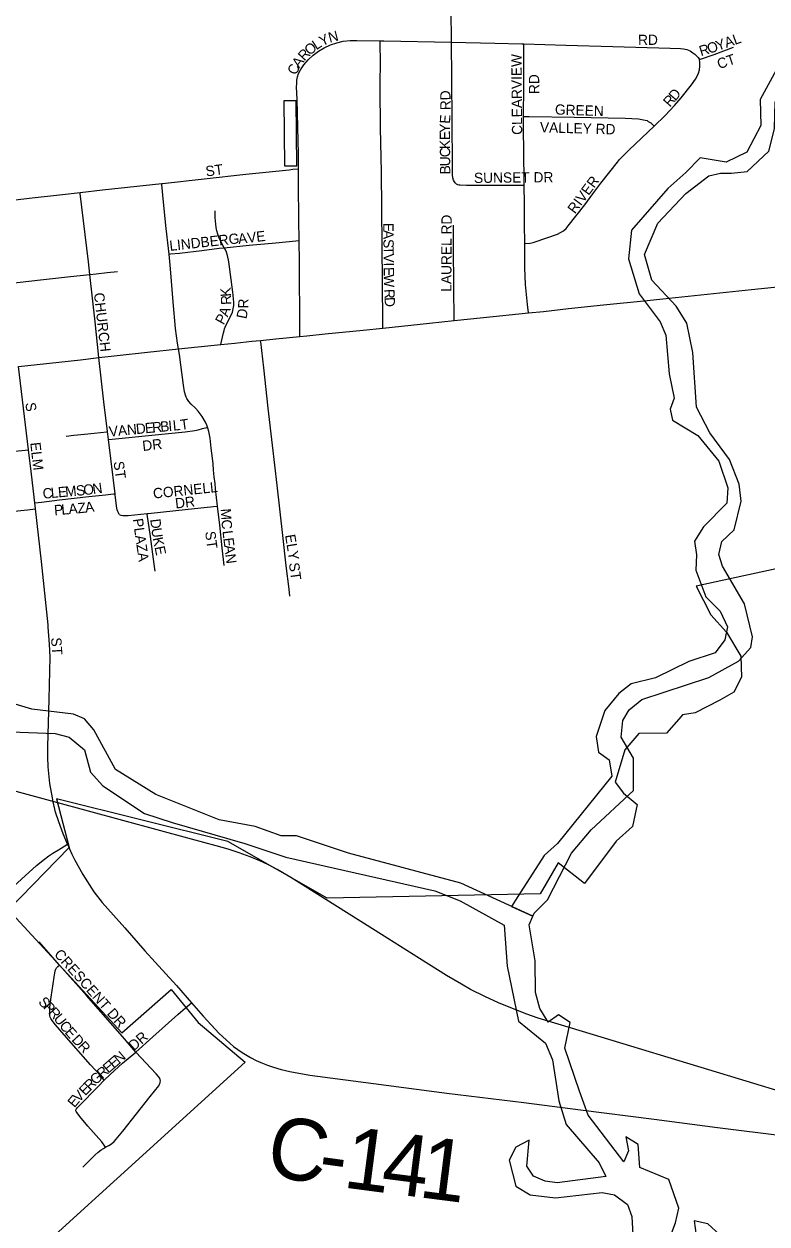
# Model space of a CAD drawing. Extents: x -51392 to 1635000, y 156707 to 696232.
# Drawn here: x 142661 to 146279, y 483748 to 489592 of the extents above; entities that cross this region are included whole.
import ezdxf

# ---------------------------------------------------------------- set-up
doc = ezdxf.new("R2010")
doc.units = 0
for name, color, linetype in [('GM_X_City_Street', 7, 'Continuous'), ('GM_X_City_Street_Text', 7, 'Continuous'), ('GM_X_Corporation', 7, 'Continuous'), ('GM_X_County_Road', 7, 'Continuous'), ('GM_X_County_Road_Text', 7, 'Continuous'), ('GM_X_Major_River', 7, 'Continuous'), ('GM_X_Minor_River', 7, 'Continuous'), ('GM_X_Rail_Line', 7, 'Continuous'), ('GM_X_US_Route', 7, 'Continuous')]:
    doc.layers.add(name, color=color, linetype=linetype)

msp = doc.modelspace()

# ---------------------------------------------------------------- linework, layer by layer
at = {"layer": 'GM_X_City_Street'}
for points in [[(144742.3, 489503.6), (144741.9, 489542.5), (144741.1, 489624.4), (144743.1, 489656.8), (144747.2, 489689.2), (144761.5, 489769.8), (144775.9, 489850.9), (144782.2, 489900), (144786.9, 489965.7), (144792.6, 490146.4), (144800.6, 490392.7), (144803.7, 490507.8), (144806.4, 490539.9), (144809.5, 490555.5), (144813.9, 490570.4), (144820.4, 490584.9), (144828.3, 490598.6), (144837.5, 490611.8), (144921.9, 490712.3), (144964.1, 490763), (144988.3, 490791.5)], [(143990.3, 489224.6), (143988.3, 489286), (143988.5, 489302.4), (143989.7, 489318.8), (143992.6, 489334.9), (143997.6, 489350.5), (144004.6, 489365.4), (144013.1, 489379.4), (144022.8, 489392.7), (144044.4, 489417.4), (144068.3, 489439.9), (144094.4, 489459.8), (144122.4, 489476.8), (144152.3, 489490.3), (144183.4, 489500.9), (144215.4, 489507.9), (144248.1, 489511.7), (144280.9, 489512.4), (144394.7, 489510.4)], [(144407.9, 488111.3), (144407.6, 488136.7), (144405.5, 488332.8), (144401, 488872.1), (144397.1, 489084.5), (144395.5, 489280.6), (144396.5, 489427.7), (144395.7, 489476.7), (144394.7, 489510.4)], [(144394.7, 489510.4), (144412.2, 489510), (144742.3, 489503.6)], [(144760.2, 488818.6), (144756.5, 488823.7), (144752.4, 488831.3), (144749.1, 488842.2), (144747.5, 488857.5), (144747.5, 488906), (144745.2, 489117), (144744, 489327.9), (144742.3, 489503.6)], [(144742.3, 489503.6), (144953.7, 489499.4), (145085.1, 489496.3), (145094, 489496.3)], [(145093.1, 489142.1), (145094, 489287.2), (145094, 489496.3)], [(145094, 489496.3), (145298.3, 489489.3), (145528.1, 489482), (145807.3, 489474.1), (145856.6, 489472.6), (145872.8, 489470.9), (145888.7, 489467.4), (145903.8, 489461.2), (145917.3, 489452), (145927.4, 489444.4), (145935, 489437.7), (145943.5, 489428.9), (145950.4, 489419.5)], [(145950.4, 489419.5), (146021, 489442.8), (146116, 489479.3)], [(145728.7, 489094.6), (145783.1, 489147.1), (145828.3, 489194.5), (145860.3, 489231.8), (145911.3, 489296), (145930.4, 489322.9), (145938.8, 489337.4), (145945.4, 489353.1), (145949.3, 489369.7), (145950.9, 489386.5), (145951.6, 489405.5), (145950.4, 489419.5)], [(143997.5, 488887.2), (143997.5, 488957.9), (143994.8, 489089.1), (143990.3, 489224.6)], [(145096, 488806.7), (145095.7, 488829.5), (145092.8, 489091.1), (145093.1, 489142.1)], [(145093.1, 489142.1), (145120.2, 489142.1), (145340.4, 489138), (145587.3, 489132.7), (145653, 489129.5), (145669.2, 489127.4), (145685.3, 489124.2), (145694.3, 489121.4), (145700.6, 489118), (145712.3, 489110.4), (145719.2, 489104.3), (145728.7, 489094.6)], [(145098.6, 488522.4), (145125.4, 488524.8), (145139.2, 488527.7), (145150, 488530.5), (145257.9, 488569), (145273.2, 488576), (145287.8, 488584.9), (145300.4, 488596.4), (145311.1, 488609.4), (145391.7, 488711.7), (145430.9, 488764.2), (145469.8, 488816.8), (145549.9, 488919.6), (145560.5, 488932), (145571.5, 488943.7), (145605.8, 488978.2), (145700.7, 489067.6), (145728.7, 489094.6)], [(143331, 488815.1), (143335.5, 488815.6), (143741.4, 488861.2), (143951.5, 488882.6), (143969.1, 488884.3), (143997.5, 488887.2)], [(143999.3, 488637.8), (143997.5, 488810.2), (143997.5, 488887.2)], [(142539.4, 488726.3), (142566.4, 488729.3), (142686, 488743.1), (142848.4, 488761.7), (142933.6, 488771.4)], [(142933.6, 488771.4), (143043.1, 488783.8), (143331, 488815.1)], [(142980.8, 488372.3), (142973.9, 488434), (142934.2, 488766.8), (142933.6, 488771.4)], [(143367.9, 488471.6), (143365, 488498.9), (143353.3, 488596.4), (143340.1, 488724.6), (143331.4, 488810.9), (143331, 488815.1)], [(144760.2, 488818.6), (144765.8, 488814), (144770.7, 488811.2), (144777.2, 488809.2), (144784, 488808), (144815.9, 488806.5), (145096, 488806.7)], [(145098.6, 488522.4), (145097, 488617.1), (145097.3, 488715.1), (145096, 488806.7)], [(143636, 488502.4), (143616.3, 488538.5), (143609.6, 488553.7), (143604.5, 488569.1), (143600.3, 488584), (143596.8, 488600.8), (143594.4, 488616.9), (143593.1, 488633.7), (143592.2, 488649.8), (143592, 488682.6)], [(144000.4, 488537), (143999.3, 488637.8)], [(144755.7, 488147.7), (144755.2, 488174.8), (144753.3, 488288.4), (144751.8, 488531.9), (144751.4, 488596.8), (144751.7, 488613)], [(143636, 488502.4), (143757, 488514.7), (143886.6, 488526.3), (143967.7, 488533.9), (144000.4, 488537)], [(144003.7, 488070.1), (144003.8, 488104.4), (144001.5, 488432.7), (144000.4, 488537)], [(143367.9, 488471.6), (143373.6, 488472.2), (143417.5, 488476.4), (143526.8, 488489.6), (143611.4, 488499.9), (143636, 488502.4)], [(143619.8, 488030.9), (143622.6, 488045), (143631.5, 488088.1), (143634.5, 488099.9), (143637.1, 488108.2), (143640, 488115.9), (143646, 488130.5), (143669, 488174), (143675.4, 488189.2), (143679.7, 488204.9), (143681.9, 488221.1), (143682.3, 488237.5), (143681.4, 488253.9), (143678.3, 488286.6), (143658.2, 488433), (143651.5, 488465.3), (143646.4, 488480.9), (143639.9, 488495.3), (143636, 488502.4)], [(145117, 488185.1), (145112.7, 488225.4), (145102.5, 488323), (145098.7, 488404.6), (145099.2, 488486.3), (145098.6, 488522.4)], [(143412.7, 488009.6), (143407.7, 488037.4), (143399.1, 488108.7), (143386.3, 488238.6), (143373.5, 488400.3), (143367.9, 488471.6)], [(142584.5, 488327.5), (142740.4, 488345.8), (142887, 488362.8), (142980.8, 488372.3)], [(142980.8, 488372.3), (143011.5, 488375.7), (143065.8, 488381.7), (143115.3, 488387.4)], [(143024.4, 487967.1), (143006.5, 488141.7), (142980.8, 488372.3)], [(143554, 487628.2), (143550.5, 487638), (143543.9, 487652.4), (143527.6, 487680.6), (143518.9, 487694.2), (143508.3, 487706.2), (143495.1, 487720.8), (143474.1, 487740.9), (143462.9, 487753.8), (143453.8, 487768.4), (143450, 487775.2), (143447, 487784.1), (143442.3, 487800.5), (143437.3, 487833.5), (143424.5, 487931.6), (143417.8, 487982.9), (143412.7, 488009.6)], [(143955.7, 486806.2), (143951.9, 486838.9), (143937.8, 486953.1), (143920.9, 487100.2), (143893, 487345.3), (143870.6, 487541.3), (143849.3, 487721), (143828.3, 487917.3), (143813.3, 488044.5), (143812.8, 488050.5)], [(143067.2, 487606.8), (143049.5, 487752), (143024.4, 487967.1)], [(142682.6, 487518.5), (142634, 487924.7)], [(142865.8, 487585.1), (142903.8, 487589.2), (142955.5, 487594.9), (143001.7, 487599.9), (143063.7, 487606.4), (143067.2, 487606.8)], [(143072, 487567.7), (143067.2, 487606.8)], [(143072, 487567.7), (143074.4, 487568), (143331.3, 487594.6), (143444.6, 487606.1), (143493, 487612.5), (143509.1, 487615.6), (143530.4, 487621.4), (143551.7, 487627.6), (143554, 487628.2)], [(143602.9, 487244), (143593.4, 487327.7), (143590.7, 487353.6), (143587.4, 487386.2), (143584.1, 487418.8), (143581.1, 487450.6), (143578.4, 487478.3), (143572.8, 487526.7), (143566.7, 487575.5), (143560.4, 487607.5), (143555.9, 487622.9), (143554, 487628.2)], [(143103.9, 487304.1), (143083.2, 487476.3), (143072, 487567.7)], [(141472.3, 487385.3), (141521.3, 487391.2), (141701.3, 487409.4), (141946.6, 487438), (142077.4, 487452.5), (142273.6, 487475.5), (142518.8, 487503.1), (142649.8, 487515.3), (142682.6, 487518.5)], [(142712.8, 487259.9), (142697, 487399.5), (142682.6, 487518.5)], [(142712.8, 487259.9), (142745.8, 487264), (142833.2, 487275.1), (142977.1, 487290.8), (143057.1, 487298.8), (143095.8, 487303.2), (143103.9, 487304.1)], [(142716, 487231.2), (142712.8, 487259.9)], [(143124.8, 487203.8), (143120.3, 487211.1), (143116.8, 487218.3), (143114.4, 487225.9), (143113.4, 487233.6), (143104.6, 487297.9), (143103.9, 487304.1)], [(141813.9, 487132.8), (141875.8, 487139.7), (142055.7, 487160.3), (142186.6, 487175.9), (142334.1, 487190.3), (142661.7, 487224.2), (142677.3, 487226.2), (142716, 487231.2)], [(142778.7, 486654.4), (142777.9, 486665.5), (142745, 486974.7), (142716, 487231.2)], [(143124.8, 487203.8), (143132.9, 487200.2), (143142.3, 487198.4), (143149.5, 487197.8), (143158.4, 487198.1), (143167.1, 487198.9), (143260.6, 487207.7)], [(143260.6, 487207.7), (143265.2, 487208.2), (143460.8, 487228.8), (143600.3, 487243.8), (143602.9, 487244)], [(143299.5, 486927.2), (143294.3, 486960.6), (143275.8, 487096.1), (143261, 487204.5), (143260.6, 487207.7)], [(143635, 486955.1), (143625.6, 487040.6), (143613.4, 487151), (143602.9, 487244)], [(142799.2, 485823.1), (142786.6, 485892.6), (142778.9, 485974.9), (142777.1, 486022.1), (142776.8, 486073.8), (142783.5, 486304.1), (142788.4, 486508.3), (142785.1, 486571), (142778.7, 486654.4)], [(142872.5, 485597), (142851, 485648.1), (142829.5, 485706.3), (142814.2, 485753.7), (142803, 485804.1), (142799.2, 485823.1)], [(142519.4, 485311.3), (142648.6, 485426.9), (142721.9, 485493), (142760.2, 485524.4), (142782.1, 485540), (142801.6, 485553.2), (142829, 485570.2), (142872.5, 485597)], [(142833.9, 485009.1), (142733.7, 485121.6)], [(142788.7, 484755.4), (142786.8, 484762.2), (142785.7, 484771.4), (142787.1, 484803.8), (142792.6, 484852.3), (142806.9, 484949.2), (142813.1, 484980.8), (142816.2, 484989.3), (142817.6, 484992.8), (142819.2, 484995.6), (142822, 484999.2), (142825.5, 485002.2), (142833.9, 485009.1)], [(143205.7, 484584.8), (143140.6, 484661.6), (142965.5, 484861.3), (142833.9, 485009.1)], [(143205.7, 484584.8), (143288, 484659.4), (143410.1, 484768.1), (143446.9, 484800.4), (143475.6, 484825.6)], [(143051.2, 484448.8), (143027.9, 484475.5), (142983.9, 484523), (142855.4, 484668.4), (142813.8, 484717.9), (142797.7, 484738.8), (142794.8, 484743.7), (142791.7, 484748.5), (142788.7, 484755.4)], [(143051.2, 484448.8), (143079.8, 484475.5), (143140.2, 484530.5), (143205.7, 484584.8)], [(143057.8, 484121.2), (143073.2, 484129.3), (143086.7, 484138.7), (143099.1, 484149.4), (143110.2, 484161.6), (143141.9, 484199.9), (143275, 484369.4), (143316.4, 484421.4), (143321.1, 484429), (143322.5, 484432.4), (143323.7, 484436), (143324.3, 484439.1), (143325, 484444.4), (143324.4, 484448.7), (143323.5, 484452), (143320.3, 484459), (143315.3, 484466.3), (143304.2, 484478.7), (143205.7, 484584.8)], [(142913.4, 484301.2), (142913.8, 484304.4), (142914.7, 484307.5), (142915.6, 484309.1), (142919.7, 484313.9), (142927.5, 484322), (143022.1, 484417.6), (143051.2, 484448.8)], [(143057.8, 484121.2), (143039.8, 484148.4), (142971.8, 484224.1), (142933.2, 484271.3), (142918.7, 484289), (142914.7, 484295.8), (142913.8, 484298.5), (142913.4, 484301.2)], [(142947.3, 484023.7), (143005.4, 484082.8), (143021.8, 484097.8), (143037.1, 484109.6), (143047, 484115.5), (143057.8, 484121.2)]]:
    msp.add_lwpolyline(points, dxfattribs=at)
at = {"layer": 'GM_X_Corporation'}
msp.add_lwpolyline([(143928.9, 488901.4), (143958.9, 488901.7), (143988.9, 488902), (143985.9, 489218), (143925.9, 489217.4)], close=True, dxfattribs=at)
msp.add_lwpolyline([(146480.6, 486972.5), (145933.4, 486853.8), (146004.8, 486715.1), (146082.1, 486629.9), (146150.6, 486512.5), (146154.6, 486411.5), (146117.7, 486338.3), (146048.8, 486299.7), (145928.7, 486237.9), (145867.6, 486227.9), (145849.3, 486206.7), (145789.9, 486137.8), (145654.9, 486137.2), (145586.3, 486057.7), (145538.8, 485899.7), (145579.9, 485845.6), (145646.1, 485790.6), (145623.7, 485682.9), (145544, 485613), (145389.5, 485406.1), (145262.1, 485507.3), (145173.9, 485355.7), (144136.4, 485335.1), (143652.4, 485610.5), (142818.7, 485818), (142880.2, 485581.6), (142585.5, 485277.6), (143136.2, 484678.1), (143377, 484889.6), (143508.5, 484728.4), (143737.8, 484535.6), (142488.7, 483402.6)], dxfattribs=at)
at = {"layer": 'GM_X_County_Road'}
for points in [[(142872.5, 485597), (142882.1, 485574.6), (142893.5, 485548.5), (142905.7, 485522.8), (142946.5, 485449.5), (143000.5, 485365.9), (143041.4, 485313.6), (143151.5, 485190.2), (143249.4, 485078.4), (143299.6, 485022.8)], [(143299.6, 485022.8), (143402.5, 484908.9)], [(143402.5, 484908.9), (143475.6, 484825.6)], [(143475.6, 484825.6), (143533.6, 484759.5), (143610.4, 484676.2), (143644.5, 484644.8), (143681.1, 484611.8), (143722.5, 484582.6), (143764.2, 484558.4)], [(143764.2, 484558.4), (143791.1, 484544.8), (143814.3, 484533.5), (143846.6, 484520.9), (143876, 484510.8), (143912.1, 484500.9), (143955.8, 484490.3), (144053, 484472.7), (144362, 484432.3), (144719.8, 484385.7), (145094.2, 484338.9), (145370.8, 484303.3), (145728.7, 484258.4), (146037.7, 484217.5), (146363.1, 484177.1)]]:
    msp.add_lwpolyline(points, dxfattribs=at)
at = {"layer": 'GM_X_Major_River'}
for points in [[(145137.7, 485246.2), (144787.1, 485407.5), (144241.4, 485553.5), (143987.6, 485638.4), (143913.5, 485638.7), (143785.6, 485683.2), (143611.7, 485715.8), (143302, 485839), (143106.4, 485961.8), (143001.1, 486154.5), (142955.3, 486208.7), (142901.3, 486230.9), (142699.3, 486255.6), (142569.4, 486294.1)], [(142292.7, 486156.7), (142812.9, 486137), (142880.9, 486118.8), (142954.7, 486056.5), (142984.3, 485948.2), (143044, 485881.9)], [(143044, 485881.9), (143247.6, 485747), (143381.5, 485702.5), (143735.3, 485601.2), (143935.1, 485534.4), (144660.9, 485369.9), (144784.8, 485321.4), (144998.4, 485202.5), (145013.6, 485004.1), (145068.6, 484735.4), (145200.2, 484628.9), (145233.9, 484546.6), (145265.2, 484348.1), (145300.7, 484231.8), (145462.1, 484045), (145493.8, 483978.8), (145257.6, 483947.5), (145197.6, 483955.7), (145141.6, 483979.9), (145109.8, 484030.1), (145120.3, 484156.3), (145056.2, 484122.4), (145023.9, 484058.4), (145055.4, 483932.1), (145125.3, 483889.8), (145249.3, 483875.4), (145475.5, 483900.7), (145535.5, 483890.5), (145599.3, 483842.2), (145621.1, 483784), (145626.7, 483665.8)], [(145776.5, 483603.2), (145833.1, 483753.3), (145849.4, 483825.4), (145799.9, 483963.8), (145660.1, 484022.3), (145650.5, 484134.6), (145590.6, 484172.8), (145604.4, 484104.7), (145582.2, 484050.6), (145407, 484277.6), (145365.4, 484393.9), (145294.2, 484604.5), (145320.7, 484728.6), (145262.8, 484766.9), (145212.6, 484731), (145172.9, 484797.2), (145151.2, 484875.4), (145149.8, 485029.7), (145120.5, 485204.1), (145137.7, 485246.2)], [(146047, 483696.5), (145991.2, 483748.8), (145923.2, 483763.1), (145932.9, 483690.9)]]:
    msp.add_lwpolyline(points, dxfattribs=at)
at = {"layer": 'GM_X_Minor_River'}
msp.add_line((145034.3, 485293.9), (145137.7, 485246.2), dxfattribs=at)
for points in [[(146051.4, 488865.7), (146105.4, 488865.5), (146181.5, 488873.3), (146287.9, 488973.2), (146314.4, 489081.3), (146318.9, 489213.5), (146515.7, 489391.2), (146635.7, 489386.8), (146706, 489442.7), (146762.3, 489514.7), (146798.6, 489580.7), (146834.9, 489654.7)], [(146710.6, 489609), (146584.2, 489515.2), (146516.1, 489499.4), (146383.8, 489429.7), (146323.5, 489367.8), (146244.9, 489223.8), (146248.4, 489097.5), (146179.9, 488967.5), (146079.6, 488919.7), (145953.6, 488940.2)], [(145953.6, 488940.2), (145883.3, 488868.3), (145795, 488790.4), (145618.1, 488588.6), (145603.5, 488448.4), (145656.9, 488277.9), (145758.4, 488141.3), (145786.1, 488077.1), (145801.4, 487888.7), (145827, 487770.5), (145806.7, 487716.4), (145818.5, 487662.3), (145942.3, 487587.8), (146043.9, 487463.2), (146087.4, 487332.8), (146083.1, 487258.7), (145968.6, 487142.9), (145926.3, 487072.9), (145936, 487006.7), (145931.7, 486932.6), (145981.2, 486802.2), (146051, 486731.9), (146086.7, 486655.6), (146072.5, 486593.6), (146026.2, 486529.6), (145897.9, 486487.9), (145735.5, 486408.3), (145617.4, 486378.6), (145557.1, 486330.7), (145488.8, 486248.8), (145446.3, 486122.7), (145458, 486046.5), (145509.8, 486008.3), (145523.5, 485928.1), (145258.1, 485600.4), (145193.8, 485542.5), (145065, 485342.5), (145034.3, 485293.9)], [(145137.7, 485246.2), (145144.7, 485262.1), (145209, 485326.1), (145326, 485554.1), (145422.5, 485668), (145629.3, 485859.7), (145627.9, 486016), (145568.3, 486118.3), (145576.6, 486200.4), (145606.9, 486252.4), (145669.1, 486302.3), (145995.7, 486409.5), (146140.1, 486489.2), (146200.4, 486555.1), (146208.6, 486607.2), (146169.2, 486767.6), (146061.8, 486952.3), (146044.1, 487008.4), (146058.3, 487072.5), (146118.6, 487128.4), (146153.2, 487268.5), (146143.5, 487350.7), (146095.9, 487471.1), (146000.4, 487601.6), (145934.8, 487726), (145917.9, 487992.6), (145888.4, 488134.9), (145836.7, 488217.2), (145717.2, 488343.8), (145681.6, 488470.2), (145746.3, 488622.2), (145882.9, 488766.1), (145995.3, 488851.9), (146051.4, 488865.7)]]:
    msp.add_lwpolyline(points, dxfattribs=at)
at = {"layer": 'GM_X_Rail_Line'}
msp.add_lwpolyline([(146416.8, 484370.5), (146139.6, 484454.4), (145327.2, 484702.1), (145163.9, 484750.2), (145104.3, 484771.5), (144970.9, 484825.2), (144905.2, 484855.7), (144835, 484889.8), (144791.1, 484915.6), (144718.4, 484958.2), (144586.3, 485041.4), (144400.9, 485158), (144072.9, 485364.6), (143959.9, 485435.5), (143893.3, 485474.4), (143851.5, 485496.3), (143809.3, 485516.5), (143761.8, 485536.2), (143709.1, 485555.9), (143654.8, 485572.8), (143595.7, 485590), (143475.8, 485622), (142807, 485803.2), (141649.3, 486119.2)], dxfattribs=at)
at = {"layer": 'GM_X_US_Route'}
for points in [[(145311.9, 488205.8), (145483.2, 488224.4), (145694.6, 488246), (145801.9, 488257.3), (146203.7, 488299.4), (146628.4, 488343), (146840.8, 488365.4), (146899.8, 488371.4), (147167.6, 488398.5), (147268.2, 488408.2), (147291.5, 488410.5), (147600.9, 488443.2), (147747.6, 488458.5), (148268.7, 488512.5), (148479.6, 488534.6), (148492.5, 488535.9)], [(143887, 488058.1), (144003.7, 488070.1), (144037.6, 488073.2), (144127.2, 488083), (144312.9, 488101.4), (144407.9, 488111.3), (144635.9, 488135.2), (144755.7, 488147.7), (144898.1, 488162.6), (145117, 488185.1), (145190.7, 488192.7), (145311.9, 488205.8)], [(142634, 487924.7), (142724.4, 487934), (142935.6, 487957), (143024.4, 487967.1), (143114.8, 487978.1), (143262.1, 487993.2), (143412.7, 488009.6), (143507.6, 488019.4), (143619.8, 488030.9), (143687.6, 488038), (143769.6, 488046.9), (143812.8, 488050.5), (143887, 488058.1)]]:
    msp.add_lwpolyline(points, dxfattribs=at)

# ---------------------------------------------------------------- texts
at = {"layer": 'GM_X_City_Street_Text'}
for s, rotation, p in [('Y', 25.03133, (144111.8, 489482.5)), ('N', 15.03069, (144149.5, 489500.3)), ('RD', 0.53856, (145650.9, 489489.6)), ('A', 19.52138, (146080.9, 489475.3)), ('L', 19.49199, (146122.3, 489490)), ('O', 40.55675, (144051.9, 489436.5)), ('L', 33.29674, (144084, 489464.1)), ('R', 16.57732, (145956.9, 489434.9)), ('O', 17.90459, (145996.1, 489446.6)), ('Y', 19.48581, (146039.4, 489460.6)), ('A', 53.66427, (144000.7, 489374.5)), ('R', 46.50025, (144025.7, 489408.7)), ('CLEARVIEW', 90.53855, (145086.8, 489052.4)), ('CT', 18.97349, (146045.9, 489371.6)), ('C', 67.98405, (143987.4, 489340.7)), ('RD', 90.53855, (145170, 489251.2)), ('RD', 90.53855, (144738.1, 489172.4)), ('R', 48.26975, (145805.3, 489184.4)), ('D', 49.28151, (145832.3, 489214.6)), ('GREEN', 358.05044, (145245.3, 489151.3)), ('E', 86.13564, (144734.6, 489105.3)), ('Y', 90.14506, (144734.8, 489062.2)), ('E', 90.50921, (144735.1, 489027.1)), ('VALLEY RD', 358.33713, (145172.4, 489064.7)), ('K', 90.50888, (144735.5, 488983.1)), ('C', 90.48996, (144735.8, 488943.5)), ('ST', 7.65852, (143548.1, 488849.3)), ('U', 90.50888, (144736.2, 488899.5)), ('B', 90.51425, (144736.6, 488859.9)), ('SUNSET DR', 0.53856, (144852, 488817.7)), ('RIVER', 53.39096, (145343.2, 488664.5)), ('LAUREL RD', 89.80096, (144741.9, 488288.1)), ('E', 270.53855, (144410, 488623.7)), ('LINDBERG', 6.25007, (143371.5, 488486.9)), ('AVE', 6.44675, (143705.7, 488520.8)), ('S', 270.53855, (144410.8, 488544.5)), ('A', 270.55391, (144410.3, 488588.5)), ('T', 270.55913, (144411.1, 488509.3)), ('V', 270.53855, (144411.5, 488474.1)), ('I', 270.54167, (144411.9, 488430.1)), ('E', 270.55913, (144412.1, 488408.1)), ('W', 271.20238, (144412.4, 488372.2)), ('K', 93.48529, (143668.8, 488265.3)), ('CHURCH', 276.44496, (143000.8, 488281.2)), ('R', 93.26329, (143671.1, 488225.5)), ('R', 89.28186, (143753.2, 488206.3)), ('R', 272.64605, (144414.3, 488300.5)), ('D', 272.637, (144416.1, 488261)), ('A', 70.10913, (143652.9, 488162.4)), ('D', 78.29419, (143743.2, 488153)), ('P', 60.86822, (143632.2, 488123.7)), ('S', 277.6602, (142666.9, 487746)), ('B', 5.37859, (143326.1, 487605.5)), ('I', 5.35301, (143365.5, 487609.2)), ('L', 5.35774, (143387.4, 487611.3)), ('T', 7.77427, (143424.8, 487614.8)), ('V', 5.37479, (143076.4, 487582.1)), ('A', 5.35301, (143120.2, 487586.2)), ('N', 5.37497, (143164, 487590.3)), ('D', 5.35301, (143207.8, 487594.4)), ('E', 5.37031, (143251.6, 487598.5)), ('R', 5.35261, (143286.6, 487601.8)), ('ELM', 276.44161, (142690.8, 487552.4)), ('DR', 6.54516, (143239.7, 487512.2)), ('ST', 277.6602, (143096.5, 487459.6)), ('C', 5.03597, (142753.6, 487279.8)), ('L', 5.05737, (142793.1, 487283.3)), ('E', 5.05038, (142828.2, 487286.4)), ('M', 5.03922, (142863.2, 487289.5)), ('S', 5.02315, (142915.8, 487294.1)), ('O', 6.30491, (142952.1, 487297.4)), ('N', 8.1041, (142997.5, 487302.4)), ('CORNELL', 5.89458, (143291.5, 487280.5)), ('P', 4.83247, (142809.2, 487199)), ('L', 4.81951, (142844.3, 487201.9)), ('A', 4.86527, (142879.4, 487204.9)), ('Z', 5.37031, (142923.7, 487208.7)), ('A', 7.57852, (142960.9, 487212.2)), ('DR', 6.55654, (143399.4, 487232)), ('M', 273.78203, (143617.9, 487230.7)), ('PLAZA', 278.12938, (143189.8, 487180.8)), ('D', 276.64707, (143275.1, 487179.5)), ('U', 277.77658, (143280.3, 487134.8)), ('C', 275.02169, (143621.4, 487176.8)), ('K', 281.31569, (143286.8, 487087.9)), ('ST', 277.6602, (143542.3, 487118.8)), ('L', 276.95993, (143626.6, 487122.4)), ('E', 277.03498, (143630.9, 487087.4)), ('ELY', 279.28788, (143931.4, 487102.5)), ('E', 281.85461, (143295.6, 487044.3)), ('A', 277.02114, (143635.2, 487052.5)), ('N', 277.02114, (143640.6, 487008.8)), ('ST', 277.6602, (143950.3, 486966)), ('ST', 274.11319, (142792.1, 486602.6)), ('CRESCENT DR', 311.72641, (142804.4, 485059.3)), ('S', 313.81923, (142727.1, 484825.8)), ('P', 313.79933, (142751.4, 484800.4)), ('R', 312.91026, (142775.7, 484775.1)), ('U', 308.98672, (142802, 484746.8)), ('C', 308.40927, (142829.6, 484712.7)), ('E', 311.30636, (142856, 484679.6)), ('DR', 41.13341, (143196, 484588.8)), ('D', 313.02204, (142889.3, 484642.2)), ('R', 313.0727, (142919.4, 484610)), ('E', 40.68345, (143097.6, 484502.1)), ('N', 40.71228, (143124.3, 484525.1)), ('R', 41.74046, (143041.5, 484452.9)), ('E', 40.76046, (143070.9, 484479.1)), ('R', 45.46984, (142983.2, 484394.2)), ('G', 44.90487, (143010.9, 484422.4)), ('V', 46.1104, (142928.2, 484337.5)), ('E', 45.49991, (142958.6, 484369.1)), ('E', 50.21876, (142906.3, 484311.2))]:
    msp.add_text(s, height=50, rotation=rotation, dxfattribs=at).set_placement(p)
at = {"layer": 'GM_X_County_Road_Text'}
for s, rotation, p in [('C', 349.97188, (143829.6, 483988.5)), ('1', 352.54991, (144208.8, 483926.5)), ('4', 352.71529, (144393, 483902.4)), ('1', 352.75421, (144576.5, 483879)), ('-', 352.12757, (144084.4, 483943.7))]:
    msp.add_text(s, height=300, rotation=rotation, dxfattribs=at).set_placement(p)

doc.saveas('drawing.dxf')
